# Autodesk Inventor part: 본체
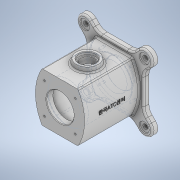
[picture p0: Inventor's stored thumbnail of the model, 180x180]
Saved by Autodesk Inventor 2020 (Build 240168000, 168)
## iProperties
Created: 2022-01
Part Number: 본체
Material: 일반
Document SubType Name: Modeling
Designer: user
Density: 1 g/cm^3
Appearance: 기본값
Mass: 458.296 g
Surface Area: 914.32 cm^2
Volume: 458.296 cm^3
Author: user
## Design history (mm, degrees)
sketch "스케치1"
  geometry: L1 (-53, -53)-(53, -53); L2 (53, -53)-(53, 53); L3 (53, 53)-(-53, 53); L4 (-53, 53)-(-53, -53); L5 (-53, -53)-(53, 53); L6 (53, -53)-(-53, 53); L7 (-54.447, -54.447)-(54.447, 54.447); L8 (-43.841, -65.054)-(65.054, 43.841); L9 (43.841, 65.054)-(-65.054, -43.841); L10 (-54.447, 54.447)-(54.447, -54.447); L11 (-65.054, 43.841)-(43.841, -65.054); L12 (65.054, -43.841)-(-43.841, 65.054); A1 r 15 centre (-54.447, -54.447) between (-65.054, -43.841) and (-43.841, -65.054); A2 r 15 centre (54.447, 54.447) between (65.054, 43.841) and (43.841, 65.054); A3 r 15 centre (-54.447, 54.447) between (-43.841, 65.054) and (-65.054, 43.841); A4 r 15 centre (54.447, -54.447) between (43.841, -65.054) and (65.054, -43.841); 9 further points
  constraints: 28 end point, 8 point on circle, 8 tangent, 4 centre point, 4 midpoint, 4 parallel, 2 point on line, 1 horizontal, 1 perpendicular
  dimensions: "d21" = 106 distance of L3.end L2.end; "d22" = 106 distance of L2.end L1.end; "d23" = 30 diameter of A2; "d24" = 30 distance between parallel lines of L11 L12; "d25" = 154 distance of L10.end L10.start; "d26" = 154 distance of L7.end L7.start
node "작업 평면1"
sketch "스케치2"
  geometry: L1 (-32.942, -45)-(0, -45); L2 (0, 45)-(-32.942, 45); L3 (0, 45)-(32.942, 45); L4 (32.942, -45)-(0, -45); A1 r 90 centre (45, 0) between (-32.942, 45) and (-32.942, -45); A2 r 90 centre (-45, 0) between (32.942, -45) and (32.942, 45)
  constraints: 8 end point, 4 point on circle, 2 centre point, 1 horizontal, 1 parallel
extrude "돌출2" join sketch "스케치2" distance "d13" = 100; taper "d14" = 0 deg
extrude "돌출3" join sketch "스케치1" distance "d27" = 10; taper "d28" = 0 deg
fillet "모깎기2" dims "d29" = 20
sketch "스케치4"
  geometry: L1 (45, 110)-(-45, 110) reference; L2 (0, 110)-(0, 0); L3 (0, 110)-(25, 110); L4 (25, 110)-(25, 98); L5 (25, 98)-(37, 98); L6 (37, 98)-(37, 12); L7 (37, 12)-(25, 12); L8 (25, 12)-(25, 0); L9 (23.503, 0)-(37.645, 0) reference; L10 (25, 0)-(0, 0); L11 (23.503, 0)-(23.503, 10) reference; 1 further point
  constraints: 16 end point, 4 perpendicular, 2 point on line, 1 horizontal, 1 midpoint, 1 parallel, 1 vertical
  dimensions: "d30" = 25 distance of L2.start L3.end; "d31" = 12 distance of L3.end L4.end; "d32" = 12 distance of L4.end L5.end; "d33" = 86 distance of L5.end L6.end
revolve "회전2" sketch "스케치4" stored, may be unused: angle "d34" = 90 deg
node "작업 평면2"
sketch "스케치5"
  geometry: L1 (0, 0)-(0, 60); C1 r 20 at (0, 60)
  constraints: 2 end point, 1 centre point, 1 coincident, 1 vertical
  dimensions: "d36" = 60 distance of L1.start L1.end; "d37" = 40 diameter of C1
extrude "돌출4" join sketch "스케치5" stored distance "d38" = 10; taper "d39" = 15 deg
sketch "스케치6"
  geometry: C1 r 20 at (0, 0) reference; 2 further points
  constraints: 1 coincident
hole "구멍1" sketch "스케치6" at (0, 0) diameter "d40" = 24; stored, may be unused: countersink angle "d44" = 90 deg, drill point angle "d46" = 0 deg; dims "d41" = 8, "d42" = 30, "d43" = 5, "d45" = 39.5
chamfer "모따기1" distance "d47" = 1; stored, may be unused: second distance "d48" = 2, angle "d49" = 45 deg
chamfer "모따기3" distance "d53" = 1; stored, may be unused: second distance "d54" = 2, angle "d55" = 45 deg
sketch "스케치7"
  geometry: 1 further point
sketch "스케치8"
  geometry: A1 r 15 centre (-54.447, 54.447) between (-43.841, 65.054) and (-65.054, 43.841) reference; A2 r 15 centre (54.447, 54.447) between (65.054, 43.841) and (43.841, 65.054) reference; A3 r 15 centre (54.447, -54.447) between (43.841, -65.054) and (65.054, -43.841) reference; A4 r 15 centre (-54.447, -54.447) between (-65.054, -43.841) and (-43.841, -65.054) reference; 5 further points
  constraints: 4 coincident
hole "구멍2" sketch "스케치8" at (-54.447, 54.447), (54.447, 54.447), (54.447, -54.447), (-54.447, -54.447) diameter "d56" = 9; stored, may be unused: countersink angle "d60" = 90 deg, drill point angle "d62" = 0 deg; dims "d57" = 8, "d58" = 18, "d59" = 2, "d61" = 39.5
sketch "스케치9"
  geometry: L1 (0, 0)-(-46.362, 46.362); L2 (0, 0)-(65.566, 0); L3 (0, 0)-(0, 40); A1 r 40 centre (0, 0) between (0, 40) and (-28.284, 28.284); 1 further point
  constraints: 6 end point, 2 point on circle, 1 centre point, 1 coincident, 1 equal length, 1 horizontal, 1 point on line, 1 vertical
  dimensions: "d63" = 80 diameter of A1; "d65" = 45 deg angle of L1 L3
hole "구멍3" sketch "스케치9" at (-28.284, 28.284) diameter "d66" = 3.242; stored, may be unused: countersink angle "d70" = 90 deg, drill point angle "d72" = 118 deg; dims "d67" = 8, "d68" = 18, "d69" = 2, "d71" = 10
sketch "스케치10"
  geometry: L1 (0, 0)-(-44.978, 44.978); L2 (0, 0)-(63.609, 0); C1 r 25 at (0, 0) reference; C2 r 40 at (0, 0); C3 r 1.621 at (-28.284, 28.284) reference; 2 further points
  constraints: 4 end point, 2 coincident, 1 centre point, 1 equal length, 1 horizontal
  dimensions: "d76" = 80 diameter of C2; "d77" = 135 deg angle of L2 L1
hole "구멍4" sketch "스케치10" at (-28.284, 28.284) diameter "d78" = 3.242; stored, may be unused: countersink angle "d82" = 90 deg, drill point angle "d84" = 118 deg; dims "d79" = 8, "d80" = 18, "d81" = 2, "d83" = 10
fillet "모깎기3" dims "d88" = 3
fillet "모깎기4" dims "d89" = 3
fillet "모깎기5" dims "d90" = 3
chamfer "모따기4" distance "d91" = 1; stored, may be unused: second distance "d92" = 2, angle "d93" = 45 deg
chamfer "모따기5" distance "d94" = 1; stored, may be unused: second distance "d95" = 2, angle "d96" = 45 deg
node "작업 평면3"
sketch "스케치11"
  geometry: L1 (53, 40)-(53, 80) reference; L2 (69.447, 0)-(43.841, 0) reference; 3 further points
  constraints: 1 other
feature "엠보싱1" sketch "스케치11" dims "d21" = 106, "d22" = 106, "d23" = 30, "d24" = 30, "d25" = 154, "d26" = 154, "d98" = 0.5, "d99" = 0
fillet "모깎기6" dims "d100" = 3
node "솔리드1"
pattern_circular "원형 패턴1" dims angle "d74" = 360 deg
pattern_circular "원형 패턴2" dims angle "d86" = 360 deg
feature "A9D066F2-1C7D-4E18-AEED-F7BC21143FA4" dims "d40" = 24, "d41" = 8, "d42" = 30, "d43" = 5, "d44" = 90 deg, "d45" = 39.5, "d46" = 0
other parameters: "d35" = 53, "d97" = 45
